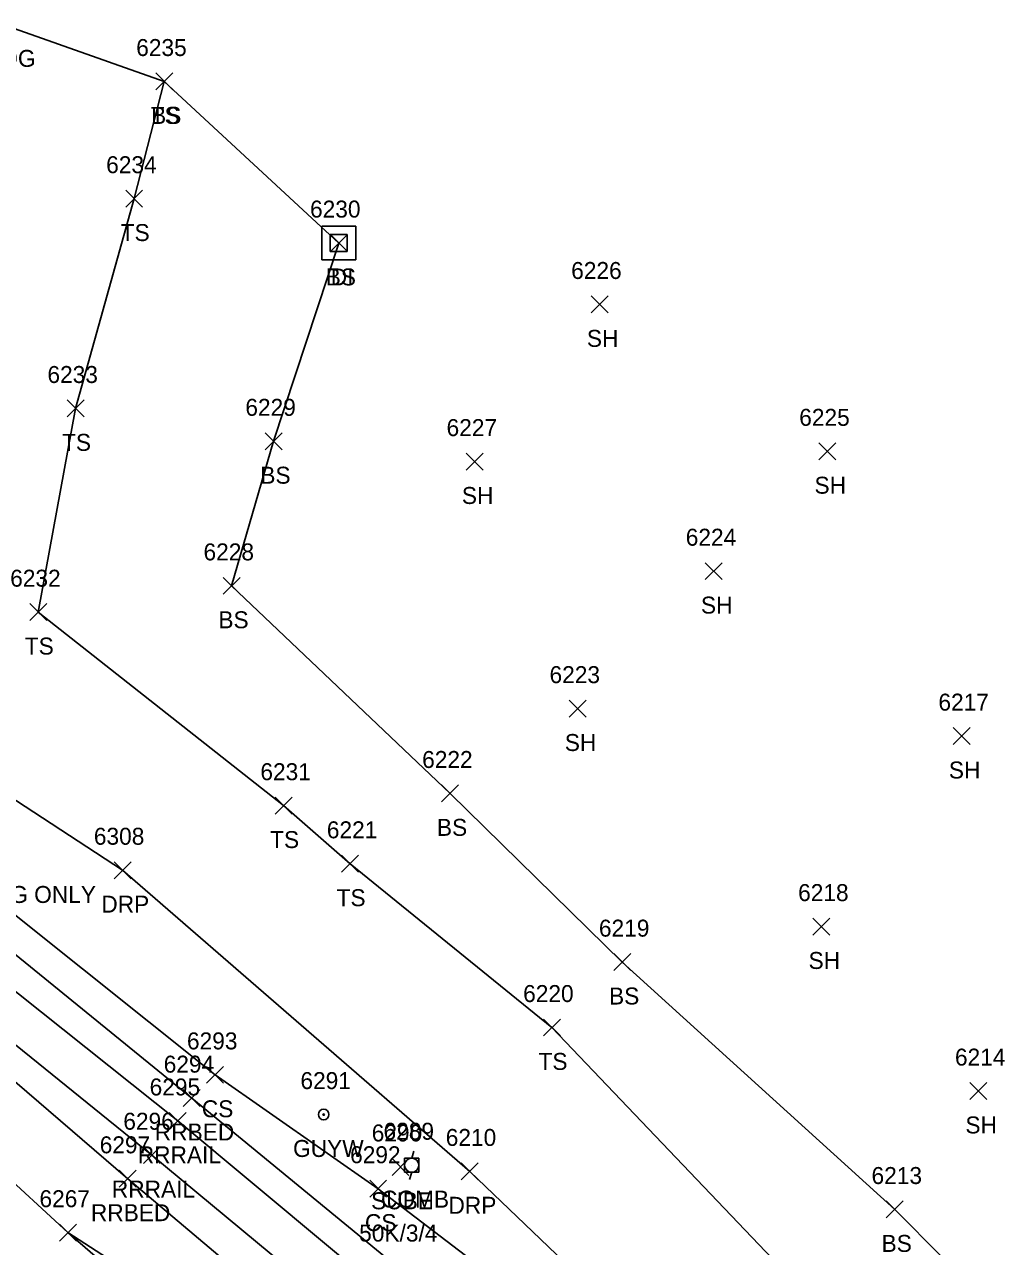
# Model space of a CAD drawing. Extents: x 1618146 to 1620418, y 640749 to 641927.
# Drawn here: x 1619767.2 to 1619881.9, y 641466.2 to 641610.3 of the extents above; entities that cross this region are included whole.
import ezdxf

# ---------------------------------------------------------------- set-up
doc = ezdxf.new("R2010")
doc.units = 0
for name, color, linetype in [('D_A', 7, 'Continuous'), ('D_I', 7, 'Continuous'), ('DS', 7, 'Continuous'), ('L_A', 7, 'Continuous'), ('L_I', 7, 'Continuous'), ('L_TIC', 7, 'Continuous'), ('LABL', 7, 'Continuous'), ('LELB', 7, 'Continuous'), ('R_A', 7, 'Continuous'), ('R_I', 7, 'Continuous'), ('R_TIC', 7, 'Continuous'), ('RDP', 7, 'Continuous'), ('RR', 7, 'Continuous'), ('RRB', 7, 'Continuous'), ('S_C', 7, 'Continuous'), ('U_A', 7, 'Continuous'), ('U_C', 7, 'Continuous'), ('U_I', 7, 'Continuous'), ('U_TIC', 7, 'Continuous'), ('UP', 7, 'Continuous'), ('UPGW', 7, 'Continuous')]:
    doc.layers.add(name, color=color, linetype=linetype)

msp = doc.modelspace()

# ---------------------------------------------------------------- linework, layer by layer
at = {"layer": 'DS'}
for p, q in [((1619802.28, 641586.54), (1619806.28, 641586.54)), ((1619802.28, 641582.54), (1619802.28, 641586.54)), ((1619806.28, 641586.54), (1619806.28, 641582.54)), ((1619803.28, 641583.54), (1619803.28, 641585.54)), ((1619803.28, 641585.54), (1619805.28, 641585.54)), ((1619804.29, 641584.54), (1619804.29, 641584.54)), ((1619804.29, 641584.54), (1619804.29, 641584.54)), ((1619805.28, 641585.54), (1619805.28, 641583.54)), ((1619805.28, 641583.54), (1619803.28, 641583.54)), ((1619806.28, 641582.54), (1619802.28, 641582.54))]:
    msp.add_line(p, q, dxfattribs=at)
at = {"layer": 'L_TIC'}
for points in [[(1619782.72, 641602.58), (1619784.72, 641604.58)], [(1619784.72, 641602.58), (1619782.72, 641604.58)], [(1619782.72, 641602.58), (1619784.72, 641604.58)], [(1619784.72, 641602.58), (1619782.72, 641604.58)], [(1619779.17, 641588.77), (1619781.17, 641590.77)], [(1619781.17, 641588.77), (1619779.17, 641590.77)], [(1619803.29, 641583.54), (1619805.29, 641585.54)], [(1619805.29, 641583.54), (1619803.29, 641585.54)], [(1619834.02, 641576.3), (1619836.02, 641578.3)], [(1619836.02, 641576.3), (1619834.02, 641578.3)], [(1619772.26, 641564.04), (1619774.26, 641566.04)], [(1619774.26, 641564.04), (1619772.26, 641566.04)], [(1619795.59, 641560.17), (1619797.59, 641562.17)], [(1619797.59, 641560.17), (1619795.59, 641562.17)], [(1619819.29, 641557.78), (1619821.29, 641559.78)], [(1619821.29, 641557.78), (1619819.29, 641559.78)], [(1619860.84, 641558.99), (1619862.84, 641560.99)], [(1619862.84, 641558.99), (1619860.84, 641560.99)], [(1619847.46, 641544.86), (1619849.46, 641546.86)], [(1619849.46, 641544.86), (1619847.46, 641546.86)], [(1619790.65, 641543.13), (1619792.65, 641545.13)], [(1619792.65, 641543.13), (1619790.65, 641545.13)], [(1619767.87, 641540.03), (1619769.87, 641542.03)], [(1619769.87, 641540.03), (1619767.87, 641542.03)], [(1619831.42, 641528.66), (1619833.42, 641530.66)], [(1619833.42, 641528.66), (1619831.42, 641530.66)], [(1619876.67, 641525.42), (1619878.67, 641527.42)], [(1619878.67, 641525.42), (1619876.67, 641527.42)], [(1619816.4, 641518.66), (1619818.4, 641520.66)], [(1619818.4, 641518.66), (1619816.4, 641520.66)], [(1619796.78, 641517.22), (1619798.78, 641519.22)], [(1619798.78, 641517.22), (1619796.78, 641519.22)], [(1619804.61, 641510.37), (1619806.61, 641512.37)], [(1619806.61, 641510.37), (1619804.61, 641512.37)], [(1619860.14, 641502.97), (1619862.14, 641504.97)], [(1619862.14, 641502.97), (1619860.14, 641504.97)], [(1619836.68, 641498.78), (1619838.68, 641500.78)], [(1619838.68, 641498.78), (1619836.68, 641500.78)], [(1619828.4, 641491.07), (1619830.4, 641493.07)], [(1619830.4, 641491.07), (1619828.4, 641493.07)], [(1619788.7, 641485.49), (1619790.7, 641487.49)], [(1619790.7, 641485.49), (1619788.7, 641487.49)], [(1619878.62, 641483.58), (1619880.62, 641485.58)], [(1619880.62, 641483.58), (1619878.62, 641485.58)], [(1619807.92, 641472.07), (1619809.92, 641474.07)], [(1619809.92, 641472.07), (1619807.92, 641474.07)], [(1619868.79, 641469.62), (1619870.79, 641471.62)], [(1619870.79, 641469.62), (1619868.79, 641471.62)], [(1619771.36, 641466.89), (1619773.36, 641468.89)], [(1619773.36, 641466.89), (1619771.36, 641468.89)], [(1619771.36, 641466.89), (1619773.36, 641468.89)], [(1619773.36, 641466.89), (1619771.36, 641468.89)]]:
    msp.add_lwpolyline(points, dxfattribs=at)
at = {"layer": 'LABL'}
msp.add_lwpolyline([(1619897.21, 641367.93), (1619884.43, 641382.4), (1619853.25, 641407.41), (1619812.86, 641441.7), (1619772.36, 641467.89), (1619746.52, 641491.7), (1619723.5, 641512.01), (1619698.77, 641530.96), (1619675.85, 641542.41), (1619646.8, 641560.5), (1619644.52, 641553.11), (1619671.66, 641528.64)], dxfattribs=at)
at = {"layer": 'LELB'}
for points in [[(1619959.82, 641357.09), (1619968.82, 641370.56), (1619944.08, 641390.01), (1619910.61, 641416.55), (1619871.74, 641447.47), (1619859.45, 641460.52), (1619829.4, 641492.07), (1619805.61, 641511.37), (1619797.78, 641518.22), (1619768.87, 641541.03), (1619773.26, 641565.04), (1619780.17, 641589.77), (1619783.72, 641603.58), (1619764.68, 641610.3)], [(1620001.62, 641448.92), (1619993.41, 641422.16), (1619984.98, 641398.34), (1619977.06, 641384.68), (1619950.18, 641400.93), (1619916.84, 641428.62), (1619892.28, 641447.99), (1619869.79, 641470.62), (1619837.68, 641499.78), (1619817.4, 641519.66), (1619791.65, 641544.13), (1619796.59, 641561.17), (1619804.29, 641584.54), (1619783.72, 641603.58)], [(1619929.64, 641366.47), (1619894.8, 641397.94), (1619868.57, 641423.65), (1619828.01, 641458.47), (1619808.92, 641473.07), (1619789.7, 641486.49), (1619758.41, 641511.46), (1619744.56, 641524.05), (1619747.43, 641531.14)], [(1619966.34, 641319.18), (1619952.77, 641322.95), (1619937.07, 641332.93), (1619914.51, 641349.83), (1619848.68, 641395.56), (1619808.65, 641436.47), (1619772.36, 641467.89)]]:
    msp.add_lwpolyline(points, dxfattribs=at)
at = {"layer": 'R_TIC'}
for points in [[(1619777.81, 641509.61), (1619779.81, 641511.61)], [(1619779.81, 641509.61), (1619777.81, 641511.61)], [(1619785.96, 641482.75), (1619787.96, 641484.75)], [(1619787.96, 641482.75), (1619785.96, 641484.75)], [(1619784.3, 641480.06), (1619786.3, 641482.06)], [(1619786.3, 641480.06), (1619784.3, 641482.06)], [(1619781.25, 641476.02), (1619783.25, 641478.02)], [(1619783.25, 641476.02), (1619781.25, 641478.02)], [(1619778.42, 641473.24), (1619780.42, 641475.24)], [(1619780.42, 641473.24), (1619778.42, 641475.24)], [(1619818.71, 641474.11), (1619820.71, 641476.11)], [(1619820.71, 641474.11), (1619818.71, 641476.11)]]:
    msp.add_lwpolyline(points, dxfattribs=at)
at = {"layer": 'RDP'}
msp.add_lwpolyline([(1620046.29, 641425.2), (1620030.82, 641393.12), (1620022.2, 641371.36), (1620020.19, 641367.26), (1619996.2, 641331.35), (1619976.43, 641344.3), (1619959.82, 641357.09), (1619936.33, 641374.65), (1619891.26, 641410.4), (1619869.71, 641427.21), (1619819.71, 641475.11), (1619778.81, 641510.61), (1619747.43, 641531.14), (1619747.1, 641530.5), (1619739.15, 641529.24), (1619712.25, 641549.2), (1619714.56, 641555.95)], dxfattribs=at)
at = {"layer": 'RR'}
for points in [[(1619890.89, 641393.62), (1619862.55, 641416.89), (1619821.51, 641450.86), (1619785.3, 641481.06), (1619755.67, 641504.7), (1619731.68, 641523.97), (1619707.65, 641542.45), (1619687.87, 641557.57), (1619658.08, 641579.36)], [(1619888.22, 641389.6), (1619859.16, 641413.43), (1619820.99, 641444.88), (1619782.25, 641477.02), (1619752.76, 641500.88), (1619728.78, 641520.01), (1619704.99, 641538.38), (1619684.69, 641553.81), (1619655.25, 641575.19)]]:
    msp.add_lwpolyline(points, dxfattribs=at)
at = {"layer": 'RRB'}
for points in [[(1619986.51, 641321.42), (1619974.99, 641328.72), (1619954.79, 641347.39), (1619947.15, 641351.81), (1619929.64, 641366.47), (1619892.95, 641395.78), (1619865.64, 641419.74), (1619823.44, 641453.76), (1619786.96, 641483.75), (1619757.14, 641507.97), (1619741.95, 641521.56), (1619734, 641527.8), (1619709.51, 641546.08), (1619691.09, 641561.17), (1619661.22, 641583.46)], [(1619977.87, 641310.92), (1619966.34, 641319.18), (1619955.14, 641328.07), (1619947.13, 641336.24), (1619940.39, 641342.13), (1619921.41, 641357.17), (1619886.68, 641385.78), (1619856.81, 641410.87), (1619815.24, 641443.99), (1619779.42, 641474.24), (1619751.61, 641498.17), (1619728.14, 641518.29), (1619703.69, 641537.28), (1619683.35, 641552.45), (1619653.86, 641573.06)]]:
    msp.add_lwpolyline(points, dxfattribs=at)
at = {"layer": 'U_TIC'}
for points in [[(1619810.55, 641474.64), (1619812.55, 641476.64)], [(1619812.55, 641474.64), (1619810.55, 641476.64)]]:
    msp.add_lwpolyline(points, dxfattribs=at)
at = {"layer": 'UP'}
for p, q in [((1619812.03, 641475.01), (1619812.03, 641476.67)), ((1619812.03, 641476.67), (1619813.7, 641476.67)), ((1619813.12, 641477.51), (1619812.87, 641476.67)), ((1619813.7, 641476.67), (1619813.7, 641475.01)), ((1619813.7, 641475.01), (1619812.03, 641475.01)), ((1619812.62, 641474.17), (1619812.87, 641475.01)), ((1619812.87, 641475.84), (1619812.87, 641475.84))]:
    msp.add_line(p, q, dxfattribs=at)
msp.add_circle((1619812.87, 641475.84), 0.833, dxfattribs=at)
at = {"layer": 'UPGW'}
for radius in [0.625, 0.0833]:
    msp.add_circle((1619802.5, 641481.81), radius, dxfattribs=at)

# ---------------------------------------------------------------- texts
at = {"layer": 'D_A'}
msp.add_text('DI', height=2, dxfattribs=at).set_placement((1619803.34, 641579.54))
at = {"layer": 'D_I'}
msp.add_text('6230', height=2, dxfattribs=at).set_placement((1619800.89, 641587.54))
at = {"layer": 'L_A'}
for s, p in [('BLDG', (1619761.27, 641605.3)), ('TS', (1619782.12, 641598.58)), ('BS', (1619782.16, 641598.58)), ('TS', (1619778.58, 641584.77)), ('BS', (1619802.73, 641579.54)), ('SH', (1619833.51, 641572.3)), ('TS', (1619771.67, 641560.04)), ('BS', (1619795.03, 641556.17)), ('SH', (1619860.33, 641554.99)), ('SH', (1619818.78, 641553.78)), ('SH', (1619846.95, 641540.86)), ('BS', (1619790.09, 641539.13)), ('TS', (1619767.28, 641536.03)), ('SH', (1619830.91, 641524.66)), ('SH', (1619876.16, 641521.42)), ('BS', (1619815.84, 641514.66)), ('TS', (1619796.19, 641513.22)), ('TS', (1619804.02, 641506.37)), ('SH', (1619859.63, 641498.97)), ('BS', (1619836.12, 641494.78)), ('TS', (1619827.81, 641487.07)), ('CS', (1619788.14, 641481.49)), ('SH', (1619878.11, 641479.58)), ('CS', (1619807.36, 641468.07)), ('BS', (1619868.23, 641465.62))]:
    msp.add_text(s, height=2, dxfattribs=at).set_placement(p)
at = {"layer": 'L_I'}
for s, p in [('6235', (1619780.41, 641606.58)), ('6235', (1619780.41, 641606.58)), ('6234', (1619776.87, 641592.77)), ('6230', (1619800.89, 641587.54)), ('6226', (1619831.66, 641580.3)), ('6233', (1619769.95, 641568.04)), ('6229', (1619793.27, 641564.17)), ('6225', (1619858.53, 641562.99)), ('6227', (1619816.98, 641561.78)), ('6224', (1619845.16, 641548.86)), ('6228', (1619788.34, 641547.13)), ('6232', (1619765.56, 641544.03)), ('6223', (1619829.11, 641532.66)), ('6217', (1619874.93, 641529.42)), ('6222', (1619814.1, 641522.66)), ('6231', (1619795.04, 641521.22)), ('6221', (1619802.87, 641514.37)), ('6218', (1619858.4, 641506.97)), ('6219', (1619834.93, 641502.78)), ('6220', (1619826, 641495.07)), ('6293', (1619786.39, 641489.49)), ('6214', (1619876.88, 641487.58)), ('6292', (1619805.61, 641476.07)), ('6213', (1619867.05, 641473.62)), ('6267', (1619769.01, 641470.89)), ('6267', (1619769.01, 641470.89))]:
    msp.add_text(s, height=2, dxfattribs=at).set_placement(p)
at = {"layer": 'R_A'}
for s, p in [('DRP', (1619776.3, 641505.61)), ('RRBED', (1619782.6, 641478.75)), ('RRRAIL', (1619780.59, 641476.06)), ('RRRAIL', (1619777.54, 641472.02)), ('DRP', (1619817.2, 641470.11)), ('RRBED', (1619775.07, 641469.24))]:
    msp.add_text(s, height=2, dxfattribs=at).set_placement(p)
at = {"layer": 'R_I'}
for s, p in [('6308', (1619775.42, 641513.61)), ('6294', (1619783.65, 641486.75)), ('6295', (1619781.99, 641484.06)), ('6296', (1619778.89, 641480.02)), ('6297', (1619776.11, 641477.24)), ('6210', (1619816.88, 641478.11))]:
    msp.add_text(s, height=2, dxfattribs=at).set_placement(p)
at = {"layer": 'S_C'}
msp.add_text('PERMIT PARKING ONLY', height=2, dxfattribs=at).set_placement((1619744.76, 641506.75))
at = {"layer": 'U_A'}
for s, p in [('GUYW', (1619798.89, 641476.81)), ('SUBE', (1619808.09, 641470.64)), ('COMB', (1619809.25, 641470.84))]:
    msp.add_text(s, height=2, dxfattribs=at).set_placement(p)
at = {"layer": 'U_C'}
msp.add_text('50K/3/4', height=2, dxfattribs=at).set_placement((1619806.68, 641466.84))
at = {"layer": 'U_I'}
for s, p in [('6291', (1619799.76, 641484.81)), ('6290', (1619808.16, 641478.64)), ('6289', (1619809.55, 641478.84))]:
    msp.add_text(s, height=2, dxfattribs=at).set_placement(p)

doc.saveas('drawing.dxf')
